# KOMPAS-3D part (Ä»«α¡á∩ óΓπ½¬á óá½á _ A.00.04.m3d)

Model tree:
1. Эскиз:1
2. Операция выдавливания:1
     Расстояние 1 = 50; Расстояние 2 = 50; На расстояние 2 = 20
3. Фаска:1
     Угол = 45; Длина 1 = 1; Длина 2 = 1
4. Эскиз:2
5. Вырезать элемент выдавливания:1
     Расстояние 2 = 9; Расстояние 1 = 9
6. Эскиз:3
7. Вырезать элемент выдавливания:2
     Расстояние 2 = 9; Расстояние 1 = 9
8. Отверстие:1
     Глубина выреза = 15; Диаметр отверстия = 6.64684; Угол конуса торца = 180; Диаметр зенковки = 9; Глубина зенковки = 1.17658; Угол зенковки = 90
9. M8
     Длина резьбы = 15; Шаг резьбы = 1.25; Номинальный диаметр резьбы = 8
10. Смещенная плоскость:1
     Расстояние = 25
11. Зеркальный массив:1
12. Экземпляр ( 1 )
13. Экземпляр ( 2 )  (with: Отверстие:1)

Referenced files in C:\Program Files (x86)\ASCON\KOMPAS-3D V15\Sys\Thread\: cil1_24705-2004.xml
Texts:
  Опорная втулка вала
  Сталь 40Х  ГОСТ 4543-71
